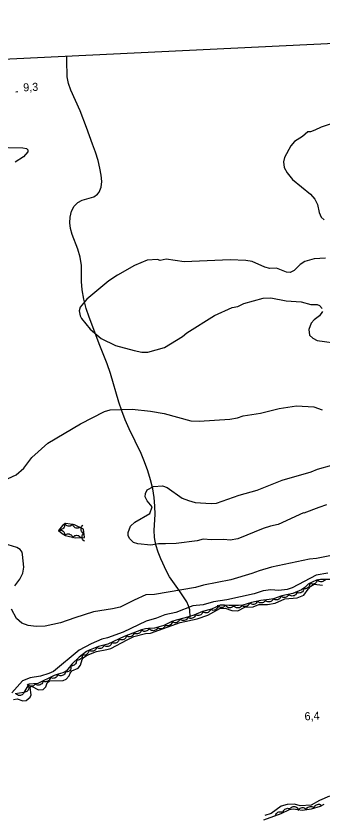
# Model space of a CAD drawing. Extents: x 336540 to 340074, y 5572036 to 5573747.
# Drawn here: x 337020.3 to 337134.3, y 5573298.8 to 5573596.5 of the extents above; entities that cross this region are included whole.
import ezdxf

# ---------------------------------------------------------------- set-up
doc = ezdxf.new("R2010")
doc.units = 0
for name, color, linetype in [('Niveau 1', 7, 'Continuous'), ('Niveau 2', 7, 'Continuous'), ('Niveau 22', 7, 'Continuous'), ('Niveau 3', 7, 'Continuous'), ('Niveau 4', 7, 'Continuous'), ('Niveau 44', 7, 'Continuous'), ('Niveau 60', 7, 'Continuous')]:
    doc.layers.add(name, color=color, linetype=linetype)

msp = doc.modelspace()

# ---------------------------------------------------------------- linework, layer by layer
at = {"layer": 'Niveau 1'}
msp.add_lwpolyline([(337011.96, 5573547.62), (337022.8, 5573547.34), (337024.18, 5573547.07), (337024.7, 5573546.59), (337024.73, 5573545.91), (337023.16, 5573543.97), (337020.02, 5573541.94)], dxfattribs=at)
at = {"layer": 'Niveau 2'}
for points in [[(337144.43, 5573558.53), (337133.95, 5573555.09), (337131.63, 5573553.96), (337129.99, 5573553.36), (337128.97, 5573553.3), (337127.02, 5573551.52), (337124.08, 5573549.67), (337122.63, 5573548.07), (337120.3, 5573543.71), (337119.89, 5573542.16), (337120.18, 5573539.96), (337121.28, 5573537.99), (337123.27, 5573535.54), (337129.99, 5573530.11), (337131.63, 5573528.16), (337132.57, 5573526.18), (337133.23, 5573523.15), (337133.99, 5573521.5), (337135.07, 5573520.53)], [(337135.63, 5573506.14), (337131.41, 5573505.92), (337127.91, 5573504.9), (337126.1, 5573503.79), (337123.85, 5573501.63), (337122.36, 5573500.87), (337121.01, 5573500.98), (337117.36, 5573502.49), (337114.84, 5573502.36), (337112.96, 5573502.76), (337108.27, 5573504.89), (337105.89, 5573505.26), (337100.12, 5573505.49), (337082.89, 5573504.77), (337076.23, 5573505.8), (337074.05, 5573505.35), (337073.03, 5573505.64), (337069.15, 5573505.43), (337064.5, 5573503.49), (337058.09, 5573499.78), (337054.83, 5573497.74), (337046.72, 5573490.87), (337044.15, 5573487.86), (337043.89, 5573486.48), (337044.15, 5573484.62), (337044.72, 5573483.64), (337047.95, 5573479.73), (337052.05, 5573476.2), (337057.41, 5573473.6), (337064.29, 5573471.74), (337067.18, 5573471.04), (337069.38, 5573471.15), (337075.57, 5573472.84), (337082.3, 5573476.91), (337083.91, 5573478.36), (337094.24, 5573484.82), (337100.87, 5573487.72), (337102.88, 5573488.16), (337105.19, 5573489.29), (337112.37, 5573491.2), (337115.23, 5573491.35), (337120.88, 5573490.28), (337126.48, 5573489.88), (337130.08, 5573488.88), (337132.47, 5573488.82), (337133.32, 5573488.55), (337134.39, 5573487.39)], [(337134.45, 5573486.21), (337133.34, 5573484.63), (337131.38, 5573483.18), (337130.28, 5573481.93), (337129.38, 5573479.52), (337129.66, 5573477.48), (337130.89, 5573476.35), (337132.48, 5573475.43), (337141.51, 5573474.19)], [(337063.55, 5573449.82), (337070.35, 5573449.14), (337075.49, 5573448.21), (337085.43, 5573445.51), (337088.49, 5573445.33), (337099.96, 5573446.07), (337102.8, 5573446.56), (337104.97, 5573447.37), (337111.35, 5573448.39), (337118.38, 5573450.09), (337124.76, 5573451.1)], [(337124.76, 5573451.1), (337131.19, 5573450.75), (337134.3, 5573449.56)], [(337017.33, 5573424), (337020.31, 5573425.36), (337023.21, 5573427.87), (337026.24, 5573431.77), (337032.21, 5573437.17), (337044.35, 5573444.41), (337053.27, 5573448.95), (337055.43, 5573449.56), (337063.55, 5573449.82)], [(337127.32, 5573411.18), (337117.9, 5573406.8), (337115.05, 5573406.15), (337112.37, 5573405.33), (337102.93, 5573401.45), (337100.09, 5573400.96), (337097.71, 5573401.17), (337093.14, 5573401.1), (337090.07, 5573401.28), (337087.75, 5573400.67), (337080.01, 5573399.74), (337075.95, 5573399.54), (337073.42, 5573399.59), (337070.56, 5573399.1), (337065.64, 5573399.53), (337064.09, 5573400.12), (337062.66, 5573401.41), (337062.1, 5573402.57), (337062.04, 5573403.75), (337062.92, 5573406.17), (337064.55, 5573407.62), (337070.13, 5573410.94), (337071.01, 5573413.38), (337069.21, 5573415.66), (337068.45, 5573417.15), (337068.57, 5573418.33), (337069.16, 5573419.71), (337071.48, 5573421.03), (337074.84, 5573421.2), (337076.57, 5573420.62), (337082.19, 5573416.67), (337084.6, 5573415.77), (337087, 5573415.04), (337092.94, 5573414.67), (337094.98, 5573414.78), (337103.45, 5573417.76), (337110.12, 5573419.64), (337119.41, 5573423.33), (337130.27, 5573426.43), (337132.58, 5573427.41), (337137.92, 5573428.87)], [(337135.96, 5573414.17), (337133.13, 5573413.18), (337127.49, 5573411.02)], [(337019.89, 5573383.92), (337021.79, 5573386.4), (337022.85, 5573388.66), (337023.27, 5573390.9), (337022.68, 5573395.62), (337022.64, 5573396.46), (337021.91, 5573397.44), (337020.68, 5573398.22), (337017.42, 5573399.24)], [(337138.47, 5573395.3), (337132.25, 5573394.13), (337129.56, 5573393.81), (337115.51, 5573390.9), (337110.83, 5573389.47), (337108.16, 5573388.47), (337100.35, 5573386.18), (337090.11, 5573384.16), (337087.12, 5573383.32), (337071.85, 5573380.67), (337068.64, 5573380.5), (337064.33, 5573378.59), (337059.05, 5573375.93), (337056.21, 5573375.28), (337049.15, 5573374.23), (337042.16, 5573372.02), (337036.85, 5573370.04), (337031.15, 5573368.91), (337027.77, 5573368.73), (337024.88, 5573369.08), (337022.48, 5573369.99), (337020.51, 5573371.76), (337018.65, 5573375.21)], [(337136.44, 5573388.58), (337132.06, 5573387.83), (337123.17, 5573383.15), (337121.36, 5573382.53), (337118.14, 5573382.2), (337115.27, 5573382.4), (337112.39, 5573382.07), (337109.07, 5573380.9), (337098.87, 5573378.65), (337093.84, 5573377.9), (337089.99, 5573376.84), (337086.13, 5573376.46), (337079.81, 5573373.96), (337075.78, 5573373.07), (337072.63, 5573371.88), (337068.82, 5573370.68), (337060.21, 5573366.65), (337054.4, 5573364.49), (337052.22, 5573364.05), (337048.26, 5573362.32), (337043.81, 5573359.88), (337034.24, 5573351.93), (337032.58, 5573351.15), (337029.42, 5573350.15), (337025.57, 5573349.61), (337022.75, 5573348.45), (337018.75, 5573344)]]:
    msp.add_lwpolyline(points, dxfattribs=at)
at = {"layer": 'Niveau 22'}
msp.add_lwpolyline([(337085.23, 5573372.19), (337085.04, 5573374.97), (337084.59, 5573376.41), (337083.87, 5573377.93), (337082.92, 5573379.48), (337081.2, 5573381.99), (337077.45, 5573387.29), (337076.33, 5573389.32), (337074.25, 5573393.94), (337073.26, 5573396.49), (337072.44, 5573399.21), (337071.92, 5573401.92), (337071.8, 5573404.63), (337072.09, 5573410.5), (337072.05, 5573413.66), (337071.78, 5573416.89), (337071.21, 5573420.15), (337070.4, 5573423.42), (337069.37, 5573426.77), (337068.22, 5573430.15), (337066.94, 5573433.31), (337062.48, 5573442.46), (337060.99, 5573445.79), (337059.69, 5573449.15), (337058.61, 5573452.47), (337055.46, 5573463.16), (337054.23, 5573466.69), (337051.53, 5573473.57), (337047.59, 5573484.1), (337046.46, 5573487.4), (337045.57, 5573490.85), (337045.01, 5573494.32), (337044.76, 5573497.51), (337044.68, 5573503.41), (337044.2, 5573506.5), (337043.34, 5573509.57), (337041.26, 5573514.97), (337040.56, 5573517.18), (337040.3, 5573519.33), (337040.46, 5573521.49), (337040.99, 5573523.66), (337041.97, 5573525.59), (337043.33, 5573526.97), (337044.97, 5573527.81), (337049.31, 5573529), (337050.72, 5573530.08), (337051.25, 5573530.85), (337051.97, 5573532.67), (337052.22, 5573534.81), (337052.06, 5573537.16), (337051.58, 5573539.7), (337050.85, 5573542.56), (337049.92, 5573545.67), (337048.86, 5573548.72), (337046.56, 5573554.99), (337044.19, 5573561.16), (337040.74, 5573568.82), (337039.85, 5573571.4), (337039.32, 5573573.82), (337039.22, 5573580), (337039.26, 5573581.61)], dxfattribs=at)
at = {"layer": 'Niveau 3'}
msp.add_line((337020.19, 5573568.28), (337020.99, 5573568.32), dxfattribs=at)
at = {"layer": 'Niveau 4'}
for points in [[(337039.03, 5573349.1), (337040.16, 5573350.33), (337040.45, 5573351.37), (337041.08, 5573352.24), (337043.4, 5573353.19), (337044.38, 5573354.26), (337044.96, 5573356.47), (337045.43, 5573357.18), (337046.76, 5573358.08), (337050.25, 5573359.41), (337054.11, 5573360.1), (337055.62, 5573360.49), (337061.73, 5573363.81), (337064.22, 5573364.95), (337068.56, 5573366.16), (337070.42, 5573366.24), (337081.42, 5573370.28), (337087.8, 5573371.56), (337091.79, 5573372.94), (337096.25, 5573375.5), (337098.27, 5573375.59), (337100.67, 5573374.67), (337102.88, 5573374.61), (337105.53, 5573375.91), (337108.58, 5573376.04), (337110.74, 5573376.98), (337113.95, 5573376.94), (337116.8, 5573377.4), (337120.45, 5573379.09), (337125.01, 5573379.47), (337127.51, 5573380.42), (337129.1, 5573382.7), (337130.07, 5573383.75), (337131.39, 5573384.49), (337134.45, 5573384.12)], [(337019.39, 5573341.45), (337020.73, 5573341.69), (337022.8, 5573340.94), (337024.14, 5573341.16), (337025.61, 5573342.41), (337025.91, 5573343.26), (337025.63, 5573345.96), (337026.11, 5573346.51), (337028.7, 5573345.09), (337030.4, 5573345.17), (337031.36, 5573346.21), (337031.97, 5573347.77), (337032.78, 5573348.49), (337037.87, 5573348.53), (337039.03, 5573349.1)], [(337137.03, 5573305.38), (337133.37, 5573303.85), (337130.24, 5573302.03), (337126.18, 5573301.85), (337123.97, 5573302.44), (337121.26, 5573302.32), (337119.09, 5573301.7), (337115.31, 5573299.01), (337112.98, 5573298.22)]]:
    msp.add_lwpolyline(points, dxfattribs=at)
at = {"layer": 'Niveau 44'}
for points in [[(337036.09, 5573404.59), (337037.44, 5573403.49), (337038.75, 5573402.65), (337042.29, 5573401.87), (337045.77, 5573401.91), (337045.41, 5573405.1), (337042.09, 5573406.72), (337038.81, 5573407.19), (337037.58, 5573406.37), (337036.09, 5573404.59)], [(337038.29, 5573407.21), (337038.4, 5573406.81), (337038.39, 5573406.4), (337038.34, 5573406.08), (337038.2, 5573405.76), (337037.98, 5573405.46), (337037.69, 5573405.21), (337037.42, 5573405.02), (337037.09, 5573404.92), (337036.72, 5573404.88), (337036.36, 5573404.91)], [(337041.4, 5573406.82), (337041.12, 5573406.51), (337040.77, 5573406.3), (337040.47, 5573406.17), (337040.12, 5573406.13), (337039.75, 5573406.15), (337039.39, 5573406.27), (337039.09, 5573406.4), (337038.83, 5573406.63), (337038.59, 5573406.92), (337038.43, 5573407.24)], [(337044.16, 5573405.71), (337043.8, 5573405.5), (337043.41, 5573405.41), (337043.08, 5573405.38), (337042.73, 5573405.45), (337042.39, 5573405.58), (337042.07, 5573405.8), (337041.83, 5573406.02), (337041.65, 5573406.32), (337041.52, 5573406.67), (337041.47, 5573407.02)], [(337045.59, 5573403.5), (337045.22, 5573403.69), (337044.93, 5573403.98), (337044.73, 5573404.24), (337044.6, 5573404.56), (337044.53, 5573404.93), (337044.55, 5573405.31), (337044.6, 5573405.63), (337044.76, 5573405.95), (337044.98, 5573406.24), (337045.25, 5573406.48)], [(337036.09, 5573404.59), (337036.49, 5573404.71), (337036.9, 5573404.71), (337037.22, 5573404.66), (337037.54, 5573404.52), (337037.85, 5573404.31), (337038.1, 5573404.02), (337038.29, 5573403.76), (337038.4, 5573403.42), (337038.45, 5573403.05), (337038.42, 5573402.69)], [(337038.46, 5573402.71), (337038.76, 5573403), (337039.13, 5573403.18), (337039.44, 5573403.29), (337039.79, 5573403.31), (337040.16, 5573403.26), (337040.51, 5573403.11), (337040.8, 5573402.96), (337041.04, 5573402.71), (337041.26, 5573402.4), (337041.39, 5573402.07)], [(337045.93, 5573400.52), (337045.56, 5573400.71), (337045.27, 5573401), (337045.06, 5573401.26), (337044.94, 5573401.58), (337044.86, 5573401.95), (337044.89, 5573402.33), (337044.94, 5573402.65), (337045.1, 5573402.96), (337045.32, 5573403.26), (337045.59, 5573403.5)], [(337041.37, 5573401.86), (337041.6, 5573402.21), (337041.91, 5573402.47), (337042.19, 5573402.64), (337042.53, 5573402.74), (337042.9, 5573402.77), (337043.28, 5573402.71), (337043.59, 5573402.63), (337043.89, 5573402.44), (337044.16, 5573402.19), (337044.37, 5573401.89)], [(337133.74, 5573386.29), (337132.24, 5573385.99), (337130.62, 5573385.31), (337129.17, 5573384.49), (337127.87, 5573383.32), (337126.65, 5573382.38), (337123.41, 5573381.01), (337119.28, 5573380.2), (337116.15, 5573379.08), (337114.58, 5573378.76), (337111.44, 5573378.39), (337107.99, 5573377.73), (337104.76, 5573376.73), (337103.2, 5573376.53), (337099.73, 5573376.57), (337097.98, 5573376.73), (337096.29, 5573376.68), (337093.12, 5573375.24), (337089.81, 5573374.38), (337086.59, 5573372.96), (337083.3, 5573371.96), (337079.96, 5573371.08), (337078.4, 5573370.54), (337075.39, 5573369.05), (337071.86, 5573368.06), (337068.55, 5573367.84), (337067.02, 5573367.45), (337060.65, 5573364.96), (337054.48, 5573362.14), (337051.07, 5573361.25), (337047.95, 5573360.07), (337046.51, 5573359.34), (337043.89, 5573357.34), (337041.25, 5573354.8), (337039.15, 5573352.22), (337037.74, 5573351.4), (337036.05, 5573350.95), (337034.57, 5573350.4), (337028.39, 5573347.52), (337025.12, 5573347.21), (337023.23, 5573344.16), (337019.97, 5573343.57)], [(337132.45, 5573386.08), (337132.37, 5573385.67), (337132.17, 5573385.31), (337131.98, 5573385.04), (337131.7, 5573384.83), (337131.37, 5573384.66), (337131, 5573384.57), (337130.68, 5573384.53), (337130.33, 5573384.59), (337129.98, 5573384.72), (337129.68, 5573384.92)], [(337135.44, 5573386.28), (337135.2, 5573385.94), (337134.88, 5573385.68), (337134.6, 5573385.51), (337134.26, 5573385.42), (337133.89, 5573385.39), (337133.51, 5573385.46), (337133.2, 5573385.55), (337132.91, 5573385.74), (337132.64, 5573386), (337132.44, 5573386.3)], [(337137.26, 5573386.27), (337133.74, 5573386.29)], [(337127.51, 5573382.75), (337127.43, 5573382.34), (337127.24, 5573381.98), (337127.05, 5573381.71), (337126.77, 5573381.49), (337126.44, 5573381.32), (337126.07, 5573381.23), (337125.75, 5573381.19), (337125.4, 5573381.25), (337125.05, 5573381.38), (337124.75, 5573381.58)], [(337129.65, 5573384.92), (337129.71, 5573384.51), (337129.65, 5573384.11), (337129.55, 5573383.79), (337129.36, 5573383.5), (337129.11, 5573383.23), (337128.78, 5573383.02), (337128.49, 5573382.88), (337128.14, 5573382.83), (337127.77, 5573382.83), (337127.42, 5573382.92)], [(337118.96, 5573380.09), (337118.86, 5573379.68), (337118.65, 5573379.33), (337118.44, 5573379.08), (337118.15, 5573378.88), (337117.82, 5573378.72), (337117.44, 5573378.66), (337117.11, 5573378.63), (337116.77, 5573378.72), (337116.43, 5573378.86), (337116.14, 5573379.08)], [(337121.89, 5573380.71), (337121.73, 5573380.33), (337121.47, 5573380.02), (337121.23, 5573379.79), (337120.91, 5573379.64), (337120.56, 5573379.54), (337120.17, 5573379.53), (337119.85, 5573379.55), (337119.52, 5573379.69), (337119.21, 5573379.88), (337118.95, 5573380.14)], [(337124.84, 5573381.29), (337124.67, 5573380.91), (337124.41, 5573380.59), (337124.17, 5573380.37), (337123.85, 5573380.22), (337123.5, 5573380.11), (337123.12, 5573380.1), (337122.79, 5573380.13), (337122.46, 5573380.26), (337122.15, 5573380.46), (337121.89, 5573380.71)], [(337095.5, 5573376.32), (337095.43, 5573375.91), (337095.25, 5573375.55), (337095.07, 5573375.27), (337094.79, 5573375.05), (337094.47, 5573374.87), (337094.1, 5573374.77), (337093.78, 5573374.72), (337093.43, 5573374.78), (337093.08, 5573374.89), (337092.77, 5573375.08)], [(337098.43, 5573376.74), (337098.2, 5573376.39), (337097.89, 5573376.13), (337097.62, 5573375.94), (337097.28, 5573375.84), (337096.91, 5573375.8), (337096.53, 5573375.85), (337096.22, 5573375.93), (337095.92, 5573376.12), (337095.64, 5573376.36), (337095.43, 5573376.65)], [(337101.42, 5573376.55), (337101.18, 5573376.21), (337100.86, 5573375.95), (337100.58, 5573375.79), (337100.24, 5573375.7), (337099.87, 5573375.67), (337099.49, 5573375.74), (337099.18, 5573375.83), (337098.89, 5573376.03), (337098.62, 5573376.28), (337098.42, 5573376.59)], [(337104.42, 5573376.52), (337104.18, 5573376.17), (337103.86, 5573375.92), (337103.58, 5573375.75), (337103.24, 5573375.67), (337102.87, 5573375.64), (337102.49, 5573375.71), (337102.18, 5573375.8), (337101.89, 5573376), (337101.62, 5573376.25), (337101.42, 5573376.55)], [(337107.29, 5573377.51), (337107.17, 5573377.11), (337106.94, 5573376.77), (337106.72, 5573376.53), (337106.42, 5573376.34), (337106.08, 5573376.2), (337105.7, 5573376.15), (337105.38, 5573376.14), (337105.04, 5573376.24), (337104.7, 5573376.4), (337104.42, 5573376.63)], [(337110.21, 5573378.16), (337110.05, 5573377.77), (337109.79, 5573377.46), (337109.54, 5573377.24), (337109.23, 5573377.09), (337108.87, 5573376.99), (337108.49, 5573376.98), (337108.16, 5573377.01), (337107.84, 5573377.14), (337107.52, 5573377.34), (337107.27, 5573377.59)], [(337113.18, 5573378.6), (337112.99, 5573378.22), (337112.7, 5573377.93), (337112.44, 5573377.73), (337112.12, 5573377.6), (337111.76, 5573377.52), (337111.37, 5573377.54), (337111.05, 5573377.59), (337110.74, 5573377.75), (337110.44, 5573377.97), (337110.2, 5573378.24)], [(337116.14, 5573379.08), (337115.98, 5573378.69), (337115.72, 5573378.38), (337115.48, 5573378.15), (337115.16, 5573378), (337114.81, 5573377.89), (337114.43, 5573377.88), (337114.1, 5573377.9), (337113.77, 5573378.03), (337113.46, 5573378.23), (337113.2, 5573378.48)], [(337089.85, 5573374.4), (337089.77, 5573373.98), (337089.59, 5573373.62), (337089.4, 5573373.35), (337089.12, 5573373.13), (337088.8, 5573372.95), (337088.43, 5573372.86), (337088.1, 5573372.81), (337087.76, 5573372.87), (337087.41, 5573372.99), (337087.1, 5573373.19)], [(337092.75, 5573375.14), (337092.61, 5573374.75), (337092.37, 5573374.42), (337092.14, 5573374.19), (337091.83, 5573374.01), (337091.49, 5573373.89), (337091.1, 5573373.86), (337090.78, 5573373.86), (337090.44, 5573373.98), (337090.12, 5573374.15), (337089.85, 5573374.39)], [(337078.49, 5573370.58), (337078.43, 5573370.17), (337078.26, 5573369.8), (337078.09, 5573369.52), (337077.82, 5573369.29), (337077.51, 5573369.1), (337077.14, 5573368.99), (337076.82, 5573368.93), (337076.47, 5573368.97), (337076.12, 5573369.08), (337075.8, 5573369.25)], [(337081.33, 5573371.55), (337081.22, 5573371.15), (337081.01, 5573370.81), (337080.8, 5573370.55), (337080.51, 5573370.35), (337080.17, 5573370.2), (337079.79, 5573370.14), (337079.46, 5573370.12), (337079.12, 5573370.21), (337078.78, 5573370.36), (337078.5, 5573370.57)], [(337084.26, 5573372.21), (337084.13, 5573371.82), (337083.89, 5573371.49), (337083.66, 5573371.25), (337083.35, 5573371.08), (337083, 5573370.96), (337082.62, 5573370.92), (337082.29, 5573370.93), (337081.96, 5573371.04), (337081.63, 5573371.21), (337081.36, 5573371.45)], [(337087.12, 5573373.12), (337087, 5573372.72), (337086.77, 5573372.39), (337086.55, 5573372.14), (337086.25, 5573371.95), (337085.91, 5573371.82), (337085.53, 5573371.77), (337085.2, 5573371.76), (337084.87, 5573371.86), (337084.53, 5573372.02), (337084.25, 5573372.25)], [(337067.04, 5573367.46), (337066.95, 5573367.05), (337066.75, 5573366.7), (337066.55, 5573366.43), (337066.26, 5573366.23), (337065.93, 5573366.06), (337065.56, 5573365.98), (337065.23, 5573365.95), (337064.89, 5573366.03), (337064.54, 5573366.16), (337064.25, 5573366.37)], [(337069.95, 5573368.2), (337069.81, 5573367.8), (337069.56, 5573367.48), (337069.33, 5573367.24), (337069.03, 5573367.07), (337068.68, 5573366.95), (337068.3, 5573366.92), (337067.97, 5573366.92), (337067.64, 5573367.04), (337067.31, 5573367.22), (337067.04, 5573367.46)], [(337072.98, 5573368.13), (337072.77, 5573367.77), (337072.47, 5573367.5), (337072.2, 5573367.31), (337071.87, 5573367.19), (337071.51, 5573367.14), (337071.12, 5573367.18), (337070.81, 5573367.24), (337070.5, 5573367.42), (337070.21, 5573367.65), (337069.99, 5573367.94)], [(337075.83, 5573369.17), (337075.7, 5573368.78), (337075.47, 5573368.45), (337075.24, 5573368.2), (337074.94, 5573368.03), (337074.59, 5573367.9), (337074.21, 5573367.86), (337073.88, 5573367.86), (337073.55, 5573367.96), (337073.22, 5573368.13), (337072.94, 5573368.36)], [(337061.43, 5573365.32), (337061.36, 5573364.91), (337061.18, 5573364.54), (337061, 5573364.27), (337060.73, 5573364.05), (337060.41, 5573363.86), (337060.04, 5573363.76), (337059.71, 5573363.71), (337059.36, 5573363.77), (337059.01, 5573363.88), (337058.71, 5573364.07)], [(337064.25, 5573366.37), (337064.15, 5573365.96), (337063.95, 5573365.6), (337063.75, 5573365.34), (337063.47, 5573365.13), (337063.14, 5573364.97), (337062.76, 5573364.89), (337062.44, 5573364.86), (337062.09, 5573364.93), (337061.75, 5573365.07), (337061.45, 5573365.27)], [(337053.17, 5573361.8), (337053.03, 5573361.4), (337052.79, 5573361.08), (337052.56, 5573360.84), (337052.25, 5573360.67), (337051.91, 5573360.54), (337051.52, 5573360.51), (337051.2, 5573360.51), (337050.86, 5573360.63), (337050.54, 5573360.8), (337050.27, 5573361.04)], [(337055.98, 5573362.82), (337055.91, 5573362.41), (337055.73, 5573362.05), (337055.54, 5573361.77), (337055.27, 5573361.55), (337054.95, 5573361.37), (337054.58, 5573361.27), (337054.26, 5573361.22), (337053.91, 5573361.27), (337053.56, 5573361.39), (337053.25, 5573361.58)], [(337058.71, 5573364.07), (337058.64, 5573363.66), (337058.46, 5573363.29), (337058.27, 5573363.02), (337058, 5573362.8), (337057.68, 5573362.62), (337057.31, 5573362.52), (337056.98, 5573362.47), (337056.64, 5573362.52), (337056.28, 5573362.64), (337055.98, 5573362.82)], [(337047.4, 5573360.02), (337047.42, 5573359.6), (337047.33, 5573359.21), (337047.21, 5573358.9), (337046.99, 5573358.62), (337046.72, 5573358.37), (337046.38, 5573358.19), (337046.08, 5573358.07), (337045.73, 5573358.05), (337045.36, 5573358.08), (337045.02, 5573358.2)], [(337050.29, 5573360.96), (337050.2, 5573360.55), (337049.99, 5573360.2), (337049.79, 5573359.94), (337049.5, 5573359.73), (337049.17, 5573359.57), (337048.79, 5573359.5), (337048.47, 5573359.47), (337048.13, 5573359.55), (337047.78, 5573359.69), (337047.49, 5573359.9)], [(337042.75, 5573356.24), (337042.82, 5573355.83), (337042.77, 5573355.43), (337042.69, 5573355.11), (337042.5, 5573354.81), (337042.26, 5573354.53), (337041.94, 5573354.31), (337041.66, 5573354.16), (337041.31, 5573354.09), (337040.94, 5573354.09), (337040.59, 5573354.16)], [(337044.91, 5573358.32), (337044.98, 5573357.91), (337044.93, 5573357.51), (337044.85, 5573357.19), (337044.66, 5573356.89), (337044.42, 5573356.61), (337044.11, 5573356.39), (337043.82, 5573356.24), (337043.47, 5573356.17), (337043.1, 5573356.17), (337042.75, 5573356.24)], [(337040.67, 5573354.09), (337040.79, 5573353.69), (337040.79, 5573353.28), (337040.74, 5573352.95), (337040.6, 5573352.63), (337040.39, 5573352.33), (337040.1, 5573352.07), (337039.84, 5573351.89), (337039.5, 5573351.78), (337039.13, 5573351.73), (337038.78, 5573351.76)], [(337033.09, 5573349.71), (337033.02, 5573349.3), (337032.84, 5573348.93), (337032.66, 5573348.66), (337032.39, 5573348.43), (337032.07, 5573348.25), (337031.7, 5573348.15), (337031.38, 5573348.09), (337031.03, 5573348.14), (337030.68, 5573348.26), (337030.37, 5573348.44)], [(337035.81, 5573350.98), (337035.74, 5573350.56), (337035.56, 5573350.2), (337035.38, 5573349.92), (337035.11, 5573349.7), (337034.79, 5573349.51), (337034.42, 5573349.41), (337034.1, 5573349.36), (337033.75, 5573349.41), (337033.4, 5573349.52), (337033.09, 5573349.71)], [(337038.74, 5573351.67), (337038.61, 5573351.27), (337038.37, 5573350.94), (337038.14, 5573350.7), (337037.83, 5573350.53), (337037.48, 5573350.4), (337037.1, 5573350.37), (337036.78, 5573350.37), (337036.44, 5573350.49), (337036.12, 5573350.66), (337035.84, 5573350.89)], [(337024.84, 5573346.76), (337025.01, 5573346.38), (337025.06, 5573345.97), (337025.06, 5573345.64), (337024.96, 5573345.31), (337024.79, 5573344.98), (337024.54, 5573344.69), (337024.3, 5573344.47), (337023.98, 5573344.32), (337023.62, 5573344.22), (337023.26, 5573344.21)], [(337027.58, 5573347.44), (337027.38, 5573347.08), (337027.09, 5573346.79), (337026.82, 5573346.59), (337026.49, 5573346.47), (337026.13, 5573346.41), (337025.75, 5573346.43), (337025.42, 5573346.49), (337025.11, 5573346.66), (337024.82, 5573346.88), (337024.59, 5573347.16)], [(337030.37, 5573348.44), (337030.3, 5573348.03), (337030.12, 5573347.66), (337029.94, 5573347.39), (337029.67, 5573347.16), (337029.35, 5573346.98), (337028.98, 5573346.88), (337028.66, 5573346.83), (337028.31, 5573346.88), (337027.96, 5573346.99), (337027.65, 5573347.17)], [(337023.29, 5573344.17), (337023.12, 5573343.79), (337022.85, 5573343.48), (337022.6, 5573343.26), (337022.29, 5573343.11), (337021.93, 5573343.01), (337021.55, 5573343.01), (337021.22, 5573343.04), (337020.9, 5573343.18), (337020.58, 5573343.38), (337020.33, 5573343.64)], [(337112.59, 5573296.62), (337119.12, 5573298.93), (337122.12, 5573300.4), (337123.58, 5573300.74), (337125.3, 5573300.41), (337126.91, 5573300.24), (337130.39, 5573300.75), (337133.68, 5573301.72), (337135.13, 5573302.47)], [(337131.38, 5573301.04), (337131.51, 5573301.44), (337131.74, 5573301.78), (337131.96, 5573302.02), (337132.26, 5573302.2), (337132.61, 5573302.34), (337132.99, 5573302.38), (337133.31, 5573302.39), (337133.65, 5573302.28), (337133.98, 5573302.12), (337134.26, 5573301.89)], [(337117.01, 5573298.18), (337117.11, 5573298.59), (337117.33, 5573298.93), (337117.54, 5573299.19), (337117.83, 5573299.39), (337118.16, 5573299.54), (337118.54, 5573299.61), (337118.87, 5573299.63), (337119.21, 5573299.54), (337119.55, 5573299.4), (337119.84, 5573299.18)], [(337119.8, 5573299.26), (337119.86, 5573299.68), (337120.03, 5573300.05), (337120.21, 5573300.33), (337120.48, 5573300.56), (337120.79, 5573300.75), (337121.16, 5573300.86), (337121.48, 5573300.92), (337121.83, 5573300.87), (337122.18, 5573300.76), (337122.5, 5573300.58)], [(337122.52, 5573300.94), (337122.82, 5573301.24), (337123.17, 5573301.43), (337123.48, 5573301.55), (337123.83, 5573301.57), (337124.2, 5573301.53), (337124.56, 5573301.4), (337124.85, 5573301.25), (337125.1, 5573301.01), (337125.32, 5573300.71), (337125.47, 5573300.38)], [(337125.48, 5573300.03), (337125.66, 5573300.41), (337125.93, 5573300.71), (337126.19, 5573300.92), (337126.51, 5573301.05), (337126.87, 5573301.14), (337127.25, 5573301.13), (337127.58, 5573301.09), (337127.9, 5573300.94), (337128.2, 5573300.73), (337128.44, 5573300.46)], [(337128.44, 5573300.46), (337128.63, 5573300.84), (337128.9, 5573301.14), (337129.16, 5573301.35), (337129.48, 5573301.49), (337129.84, 5573301.57), (337130.22, 5573301.57), (337130.54, 5573301.52), (337130.86, 5573301.38), (337131.17, 5573301.17), (337131.41, 5573300.9)]]:
    msp.add_lwpolyline(points, dxfattribs=at)
at = {"layer": 'Niveau 60'}
msp.add_lwpolyline([(339458.94, 5573698.73), (339531.5, 5572199.65), (336635.22, 5572059.46), (336562.66, 5573558.54), (339458.94, 5573698.73)], dxfattribs=at)

# ---------------------------------------------------------------- texts
at = {"layer": 'Niveau 3'}
for s, p in [('9,3    ', (337023.07, 5573568.38)), ('    6,4 ', (337123.39, 5573333.48))]:
    msp.add_text(s, height=3, rotation=2.7712, dxfattribs=at).set_placement(p)

doc.saveas('drawing.dxf')
